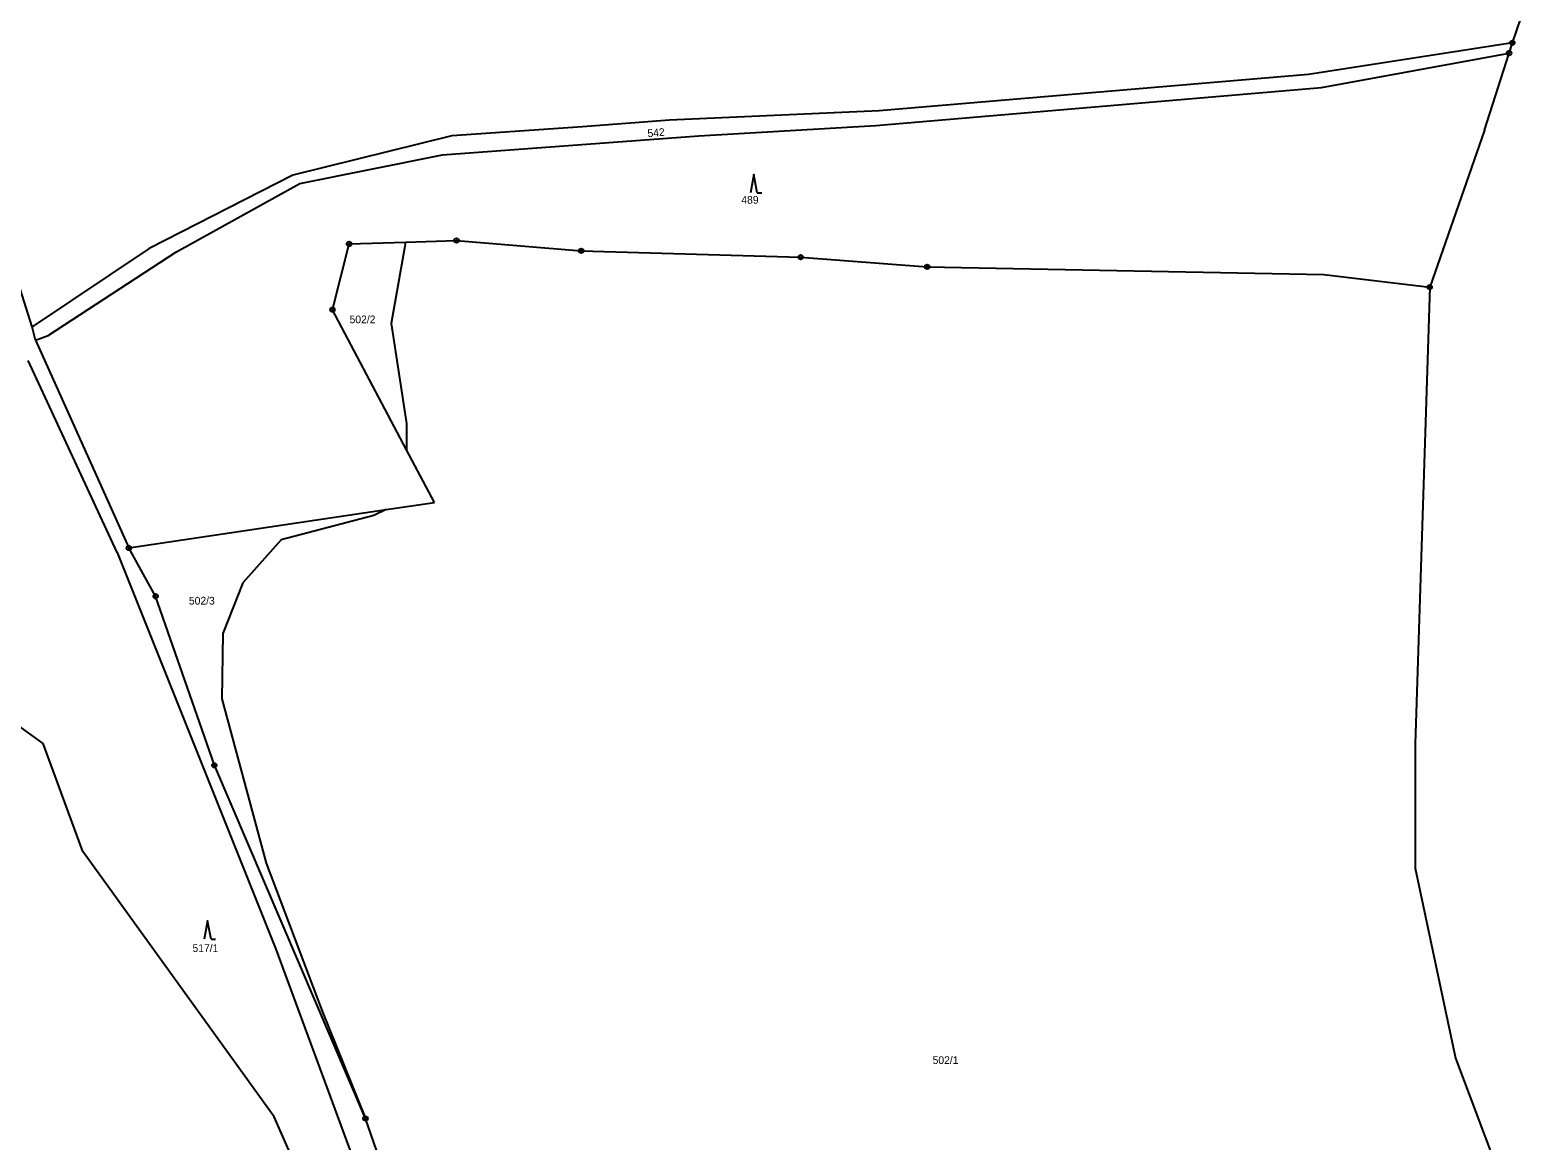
# Model space of a CAD drawing. Extents: x -885985 to -883535, y -1030025 to -1027941.
# Drawn here: x -884544.6 to -884212.6, y -1029829 to -1029584.6 of the extents above; entities that cross this region are included whole.
import ezdxf

# ---------------------------------------------------------------- set-up
doc = ezdxf.new("R2010")
doc.units = 0
doc.header["$LTSCALE"] = 0.68
for name, color, linetype, lineweight in [('1', 7, 'Continuous', 25), ('3', 7, 'Continuous', 25), ('8', 7, 'Continuous', 25)]:
    doc.layers.add(name, color=color, linetype=linetype, lineweight=lineweight)
doc.layers.add('2', color=7, linetype='Continuous')

msp = doc.modelspace()

# ---------------------------------------------------------------- linework, layer by layer
at = {"layer": '1'}
for p, q in [((-884218.22, -1029587.35), (-884216.27, -1029581.8)), ((-884218.22, -1029587.35), (-884263.14, -1029594.35)), ((-884218.94, -1029589.62), (-884218.22, -1029587.35)), ((-884260.26, -1029597.21), (-884218.94, -1029589.62)), ((-884224.33, -1029606.6), (-884218.94, -1029589.62)), ((-884263.14, -1029594.35), (-884357.69, -1029602.3)), ((-884358.41, -1029605.55), (-884260.26, -1029597.21)), ((-884357.69, -1029602.3), (-884403.86, -1029604.39)), ((-884544.19, -1029649.89), (-884558.66, -1029604.54)), ((-884423, -1029605.84), (-884451.76, -1029607.86)), ((-884403.86, -1029604.39), (-884423, -1029605.84)), ((-884397.36, -1029607.86), (-884358.41, -1029605.55)), ((-884451.76, -1029607.86), (-884486.8, -1029616.46)), ((-884453.79, -1029611.98), (-884397.36, -1029607.86)), ((-884224.33, -1029606.6), (-884236.43, -1029641.14)), ((-884485.22, -1029618.31), (-884453.79, -1029611.98)), ((-884486.8, -1029616.46), (-884518.41, -1029632.63)), ((-884512.54, -1029633.46), (-884485.22, -1029618.31)), ((-884518.41, -1029632.63), (-884544.19, -1029649.89)), ((-884478.03, -1029646.1), (-884474.39, -1029631.62)), ((-884474.39, -1029631.62), (-884461.95, -1029631.22)), ((-884462.19, -1029632.59), (-884465.15, -1029649.15)), ((-884461.95, -1029631.22), (-884462.19, -1029632.59)), ((-884461.95, -1029631.22), (-884450.74, -1029630.86)), ((-884450.74, -1029630.86), (-884423.26, -1029633.15)), ((-884540.68, -1029651.76), (-884512.54, -1029633.46)), ((-884423.26, -1029633.15), (-884374.95, -1029634.55)), ((-884374.95, -1029634.55), (-884347.07, -1029636.65)), ((-884347.07, -1029636.65), (-884259.71, -1029638.32)), ((-884259.71, -1029638.32), (-884236.43, -1029641.14)), ((-884236.43, -1029641.14), (-884239.64, -1029741.63)), ((-884461.73, -1029676.92), (-884478.03, -1029646.1)), ((-884465.15, -1029649.15), (-884461.78, -1029671.17)), ((-884543.46, -1029652.81), (-884544.19, -1029649.89)), ((-884543.46, -1029652.81), (-884540.68, -1029651.76)), ((-884543.46, -1029652.81), (-884522.89, -1029698.55)), ((-884525.46, -1029699.55), (-884545.05, -1029657.26)), ((-884461.78, -1029671.17), (-884461.73, -1029676.92)), ((-884455.6, -1029688.51), (-884461.73, -1029676.92)), ((-884466.25, -1029690.1), (-884455.6, -1029688.51)), ((-884522.89, -1029698.55), (-884466.25, -1029690.1)), ((-884468.94, -1029691.41), (-884489.35, -1029696.72)), ((-884466.25, -1029690.1), (-884468.94, -1029691.41)), ((-884516.99, -1029709.17), (-884522.89, -1029698.55)), ((-884489.35, -1029696.72), (-884497.79, -1029706.23)), ((-884525.46, -1029699.55), (-884490.51, -1029786.85)), ((-884497.79, -1029706.23), (-884502.17, -1029717.34)), ((-884504.05, -1029746.38), (-884516.99, -1029709.17)), ((-884541.78, -1029741.56), (-884580.46, -1029713.8)), ((-884502.17, -1029717.34), (-884502.4, -1029731.72)), ((-884502.4, -1029731.72), (-884492.64, -1029767.91)), ((-884532.99, -1029765.35), (-884541.78, -1029741.56)), ((-884239.64, -1029741.63), (-884239.6, -1029769.05)), ((-884470.76, -1029824.13), (-884504.05, -1029746.38)), ((-884490.88, -1029823.76), (-884532.99, -1029765.35)), ((-884492.64, -1029767.91), (-884480.32, -1029800.48)), ((-884239.6, -1029769.05), (-884230.75, -1029810.86)), ((-884490.51, -1029786.85), (-884476.99, -1029823.48)), ((-884480.32, -1029800.48), (-884470.76, -1029824.13)), ((-884230.75, -1029810.86), (-884212.61, -1029858.83)), ((-884447.21, -1029922.12), (-884490.88, -1029823.76)), ((-884476.99, -1029823.48), (-884451.73, -1029891.5)), ((-884445.79, -1029896.57), (-884470.76, -1029824.13))]:
    msp.add_line(p, q, dxfattribs=at)
at = {"layer": '3'}
for p, q in [((-884384.52, -1029620.36), (-884383.524, -1029620.36)), ((-884504.79, -1029784.63), (-884503.794, -1029784.63))]:
    msp.add_line(p, q, dxfattribs=at)
for points in [[(-884384.52, -1029620.36), (-884385.27, -1029616.36), (-884386.02, -1029620.36)], [(-884504.79, -1029784.63), (-884505.54, -1029780.63), (-884506.29, -1029784.63)]]:
    msp.add_lwpolyline(points, dxfattribs=at)
at = {"layer": '8'}
for centre, radius in [((-884218.94, -1029589.6199), 0.5), ((-884218.22, -1029587.3499), 0.5), ((-884218.22, -1029587.3499), 0.0303), ((-884218.94, -1029589.6199), 0.0303), ((-884474.39, -1029631.6199), 0.5), ((-884474.39, -1029631.6199), 0.0303), ((-884450.74, -1029630.8599), 0.5), ((-884450.74, -1029630.8599), 0.0303), ((-884423.26, -1029633.1499), 0.5), ((-884423.26, -1029633.1499), 0.0303), ((-884374.95, -1029634.5499), 0.5), ((-884374.95, -1029634.5499), 0.0303), ((-884347.07, -1029636.6499), 0.5), ((-884347.07, -1029636.6499), 0.0303), ((-884236.43, -1029641.1399), 0.5), ((-884236.43, -1029641.1399), 0.0303), ((-884478.03, -1029646.0999), 0.5), ((-884478.03, -1029646.0999), 0.0303), ((-884522.89, -1029698.5499), 0.5), ((-884522.89, -1029698.5499), 0.0303), ((-884516.99, -1029709.1699), 0.5), ((-884516.99, -1029709.1699), 0.0303), ((-884504.05, -1029746.3799), 0.5), ((-884504.05, -1029746.3799), 0.0303), ((-884470.76, -1029824.1299), 0.5), ((-884470.76, -1029824.1299), 0.0303)]:
    msp.add_circle(centre, radius, dxfattribs=at)

# ---------------------------------------------------------------- texts
at = {"layer": '2'}
msp.add_text('542', height=1.7, rotation=5, dxfattribs=at).set_placement((-884408.602, -1029608.133))
for s, p in [('489', (-884388.01, -1029622.775)), ('502/2', (-884474.28, -1029649.085)), ('502/3', (-884509.66, -1029711.005)), ('517/1', (-884508.87, -1029787.475)), ('502/1', (-884345.89, -1029812.125))]:
    msp.add_text(s, height=1.7, dxfattribs=at).set_placement(p)

doc.saveas('drawing.dxf')
